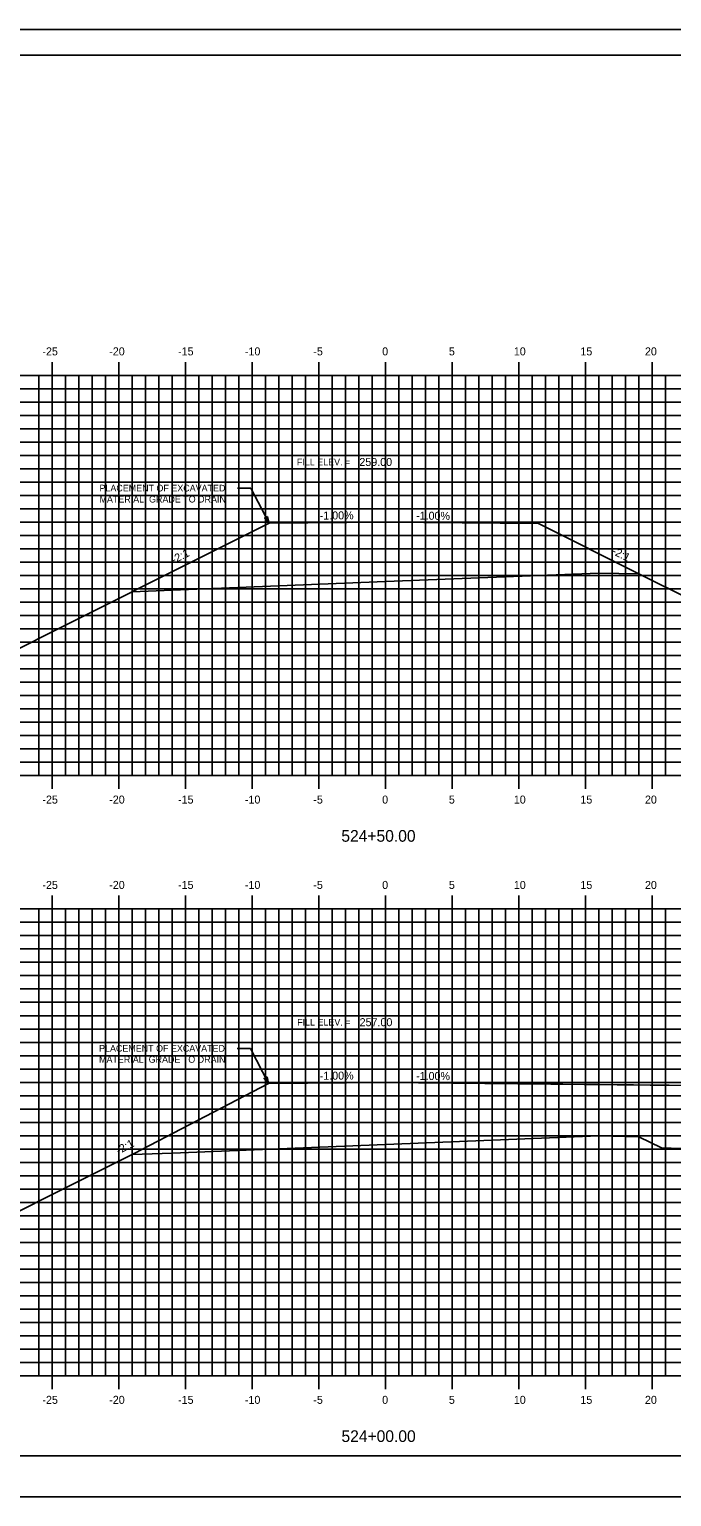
# Model space of a CAD drawing. Extents: x 1168600 to 1177589, y 610178 to 611246.
# Drawn here: x 1175478.4 to 1175526.6, y 610268.7 to 610378.7 of the extents above; entities that cross this region are included whole.
import ezdxf

# ---------------------------------------------------------------- set-up
doc = ezdxf.new("R2010")
doc.units = 0
for name, color, linetype in [('_Construction', 7, 'Continuous'), ('_Station Equation', 7, 'Continuous'), ('ANNOTATION', 7, 'Continuous'), ('BORDER', 7, 'Continuous'), ('D_Roadway_Centerline_Text', 7, 'Continuous'), ('D_Text_Standard', 7, 'Continuous'), ('H_V ANNOTATION', 7, 'Continuous'), ('MAJOR', 7, 'Continuous'), ('MINOR', 7, 'Continuous'), ('PLOT BOUNDARY', 7, 'Continuous')]:
    doc.layers.add(name, color=color, linetype=linetype)

msp = doc.modelspace()

# ---------------------------------------------------------------- linework, layer by layer
at = {"layer": '_Construction'}
for p, q in [((1175505.12, 610341.8), (1175496.39, 610341.71)), ((1175505.12, 610341.8), (1175516.58, 610341.69)), ((1175505.12, 610299.8), (1175496.36, 610299.71)), ((1175505.12, 610299.8), (1175544.81, 610299.4))]:
    msp.add_line(p, q, dxfattribs=at)
at = {"layer": '_Station Equation'}
msp.add_lwpolyline([(1175525.81, 610294.88), (1175536.74, 610294.51), (1175551.06, 610294.04), (1175553.14, 610293.97), (1175553.56, 610293.96), (1175556.21, 610293.92), (1175556.4, 610293.83), (1175559.56, 610292.31), (1175564.63, 610289.86), (1175564.65, 610290.02), (1175564.68, 610290.02), (1175565.31, 610289.71), (1175565.56, 610289.82), (1175565.82, 610289.89), (1175566.07, 610289.92), (1175566.32, 610289.9), (1175566.71, 610289.89), (1175574.47, 610289.2), (1175575.12, 610289.09)], dxfattribs=at)
at = {"layer": 'ANNOTATION'}
for p, q in [((1175494.03, 610344.35), (1175495.03, 610344.35)), ((1175496.39, 610341.71), (1175495.03, 610344.35)), ((1175494, 610302.35), (1175495, 610302.35)), ((1175496.36, 610299.71), (1175495, 610302.35))]:
    msp.add_line(p, q, dxfattribs=at)
for points in [[(1175496.27, 610342.22), (1175496.39, 610341.71), (1175496.05, 610342.1)], [(1175496.24, 610300.22), (1175496.36, 610299.71), (1175496.02, 610300.1)]]:
    msp.add_lwpolyline(points, close=True, dxfattribs=at)
at = {"layer": 'BORDER'}
for p, q in [((1175590.12, 610376.8), (1175430.12, 610376.8)), ((1175430.12, 610271.8), (1175590.12, 610271.8))]:
    msp.add_line(p, q, dxfattribs=at)
at = {"layer": 'D_Text_Standard'}
for points in [[(1175486.11, 610336.58), (1175489.54, 610338.29), (1175496.39, 610341.71), (1175505.12, 610341.8), (1175516.58, 610341.69), (1175524.11, 610337.92)], [(1175475.23, 610331.13), (1175482.58, 610334.81), (1175486.12, 610336.58), (1175489.12, 610336.7), (1175505.12, 610337.34), (1175521.12, 610337.98), (1175524.12, 610337.92), (1175528.08, 610335.94)], [(1175486.12, 610294.38), (1175486.28, 610294.47), (1175496.36, 610299.71), (1175505.12, 610299.8), (1175544.81, 610299.4), (1175552.9, 610295.5), (1175556.16, 610293.93)], [(1175473.1, 610287.88), (1175475.03, 610288.84), (1175482.58, 610292.62), (1175486.12, 610294.38), (1175489.12, 610294.5), (1175505.12, 610295.14), (1175521.12, 610295.78), (1175524.12, 610295.72), (1175525.81, 610294.88)]]:
    msp.add_lwpolyline(points, dxfattribs=at)
at = {"layer": 'MAJOR'}
for p, q in [((1175480.12, 610353.8), (1175480.12, 610352.8)), ((1175485.12, 610353.8), (1175485.12, 610352.8)), ((1175490.12, 610353.8), (1175490.12, 610352.8)), ((1175495.12, 610353.8), (1175495.12, 610352.8)), ((1175500.12, 610353.8), (1175500.12, 610352.8)), ((1175505.12, 610353.8), (1175505.12, 610352.8)), ((1175510.12, 610353.8), (1175510.12, 610352.8)), ((1175515.12, 610353.8), (1175515.12, 610352.8)), ((1175520.12, 610353.8), (1175520.12, 610352.8)), ((1175525.12, 610353.8), (1175525.12, 610352.8)), ((1175435.12, 610352.8), (1175575.12, 610352.8)), ((1175435.12, 610352.8), (1175575.12, 610352.8)), ((1175480.12, 610322.8), (1175480.12, 610352.8)), ((1175485.12, 610322.8), (1175485.12, 610352.8)), ((1175490.12, 610322.8), (1175490.12, 610352.8)), ((1175495.12, 610322.8), (1175495.12, 610352.8)), ((1175500.12, 610322.8), (1175500.12, 610352.8)), ((1175505.12, 610322.8), (1175505.12, 610352.8)), ((1175510.12, 610322.8), (1175510.12, 610352.8)), ((1175515.12, 610322.8), (1175515.12, 610352.8)), ((1175520.12, 610322.8), (1175520.12, 610352.8)), ((1175525.12, 610322.8), (1175525.12, 610352.8)), ((1175435.12, 610347.8), (1175575.12, 610347.8)), ((1175435.12, 610342.8), (1175575.12, 610342.8)), ((1175435.12, 610337.8), (1175575.12, 610337.8)), ((1175435.12, 610332.8), (1175575.12, 610332.8)), ((1175435.12, 610327.8), (1175575.12, 610327.8)), ((1175435.12, 610322.8), (1175575.12, 610322.8)), ((1175435.12, 610322.8), (1175575.12, 610322.8)), ((1175480.12, 610321.8), (1175480.12, 610322.8)), ((1175485.12, 610321.8), (1175485.12, 610322.8)), ((1175490.12, 610321.8), (1175490.12, 610322.8)), ((1175495.12, 610321.8), (1175495.12, 610322.8)), ((1175500.12, 610321.8), (1175500.12, 610322.8)), ((1175505.12, 610321.8), (1175505.12, 610322.8)), ((1175510.12, 610321.8), (1175510.12, 610322.8)), ((1175515.12, 610321.8), (1175515.12, 610322.8)), ((1175520.12, 610321.8), (1175520.12, 610322.8)), ((1175525.12, 610321.8), (1175525.12, 610322.8)), ((1175480.12, 610313.8), (1175480.12, 610312.8)), ((1175485.12, 610313.8), (1175485.12, 610312.8)), ((1175490.12, 610313.8), (1175490.12, 610312.8)), ((1175495.12, 610313.8), (1175495.12, 610312.8)), ((1175500.12, 610313.8), (1175500.12, 610312.8)), ((1175505.12, 610313.8), (1175505.12, 610312.8)), ((1175510.12, 610313.8), (1175510.12, 610312.8)), ((1175515.12, 610313.8), (1175515.12, 610312.8)), ((1175520.12, 610313.8), (1175520.12, 610312.8)), ((1175525.12, 610313.8), (1175525.12, 610312.8)), ((1175435.12, 610312.8), (1175575.12, 610312.8)), ((1175435.12, 610312.8), (1175575.12, 610312.8)), ((1175480.12, 610277.8), (1175480.12, 610312.8)), ((1175485.12, 610277.8), (1175485.12, 610312.8)), ((1175490.12, 610277.8), (1175490.12, 610312.8)), ((1175495.12, 610277.8), (1175495.12, 610312.8)), ((1175500.12, 610277.8), (1175500.12, 610312.8)), ((1175505.12, 610277.8), (1175505.12, 610312.8)), ((1175510.12, 610277.8), (1175510.12, 610312.8)), ((1175515.12, 610277.8), (1175515.12, 610312.8)), ((1175520.12, 610277.8), (1175520.12, 610312.8)), ((1175525.12, 610277.8), (1175525.12, 610312.8)), ((1175435.12, 610307.8), (1175575.12, 610307.8)), ((1175435.12, 610302.8), (1175575.12, 610302.8)), ((1175435.12, 610297.8), (1175575.12, 610297.8)), ((1175435.12, 610292.8), (1175575.12, 610292.8)), ((1175435.12, 610287.8), (1175575.12, 610287.8)), ((1175435.12, 610282.8), (1175575.12, 610282.8)), ((1175435.12, 610277.8), (1175575.12, 610277.8)), ((1175435.12, 610277.8), (1175575.12, 610277.8)), ((1175480.12, 610276.8), (1175480.12, 610277.8)), ((1175485.12, 610276.8), (1175485.12, 610277.8)), ((1175490.12, 610276.8), (1175490.12, 610277.8)), ((1175495.12, 610276.8), (1175495.12, 610277.8)), ((1175500.12, 610276.8), (1175500.12, 610277.8)), ((1175505.12, 610276.8), (1175505.12, 610277.8)), ((1175510.12, 610276.8), (1175510.12, 610277.8)), ((1175515.12, 610276.8), (1175515.12, 610277.8)), ((1175520.12, 610276.8), (1175520.12, 610277.8)), ((1175525.12, 610276.8), (1175525.12, 610277.8))]:
    msp.add_line(p, q, dxfattribs=at)
at = {"layer": 'MINOR'}
for p, q in [((1175479.12, 610322.8), (1175479.12, 610352.8)), ((1175481.12, 610322.8), (1175481.12, 610352.8)), ((1175482.12, 610322.8), (1175482.12, 610352.8)), ((1175483.12, 610322.8), (1175483.12, 610352.8)), ((1175484.12, 610322.8), (1175484.12, 610352.8)), ((1175486.12, 610322.8), (1175486.12, 610352.8)), ((1175487.12, 610322.8), (1175487.12, 610352.8)), ((1175488.12, 610322.8), (1175488.12, 610352.8)), ((1175489.12, 610322.8), (1175489.12, 610352.8)), ((1175491.12, 610322.8), (1175491.12, 610352.8)), ((1175492.12, 610322.8), (1175492.12, 610352.8)), ((1175493.12, 610322.8), (1175493.12, 610352.8)), ((1175494.12, 610322.8), (1175494.12, 610352.8)), ((1175496.12, 610322.8), (1175496.12, 610352.8)), ((1175497.12, 610322.8), (1175497.12, 610352.8)), ((1175498.12, 610322.8), (1175498.12, 610352.8)), ((1175499.12, 610322.8), (1175499.12, 610352.8)), ((1175501.12, 610322.8), (1175501.12, 610352.8)), ((1175502.12, 610322.8), (1175502.12, 610352.8)), ((1175503.12, 610322.8), (1175503.12, 610352.8)), ((1175504.12, 610322.8), (1175504.12, 610352.8)), ((1175506.12, 610322.8), (1175506.12, 610352.8)), ((1175507.12, 610322.8), (1175507.12, 610352.8)), ((1175508.12, 610322.8), (1175508.12, 610352.8)), ((1175509.12, 610322.8), (1175509.12, 610352.8)), ((1175511.12, 610322.8), (1175511.12, 610352.8)), ((1175512.12, 610322.8), (1175512.12, 610352.8)), ((1175513.12, 610322.8), (1175513.12, 610352.8)), ((1175514.12, 610322.8), (1175514.12, 610352.8)), ((1175516.12, 610322.8), (1175516.12, 610352.8)), ((1175517.12, 610322.8), (1175517.12, 610352.8)), ((1175518.12, 610322.8), (1175518.12, 610352.8)), ((1175519.12, 610322.8), (1175519.12, 610352.8)), ((1175521.12, 610322.8), (1175521.12, 610352.8)), ((1175522.12, 610322.8), (1175522.12, 610352.8)), ((1175523.12, 610322.8), (1175523.12, 610352.8)), ((1175524.12, 610322.8), (1175524.12, 610352.8)), ((1175526.12, 610322.8), (1175526.12, 610352.8)), ((1175435.12, 610351.8), (1175575.12, 610351.8)), ((1175435.12, 610350.8), (1175575.12, 610350.8)), ((1175435.12, 610349.8), (1175575.12, 610349.8)), ((1175435.12, 610348.8), (1175575.12, 610348.8)), ((1175435.12, 610346.8), (1175575.12, 610346.8)), ((1175435.12, 610345.8), (1175575.12, 610345.8)), ((1175435.12, 610344.8), (1175575.12, 610344.8)), ((1175435.12, 610343.8), (1175575.12, 610343.8)), ((1175435.12, 610341.8), (1175575.12, 610341.8)), ((1175435.12, 610340.8), (1175575.12, 610340.8)), ((1175435.12, 610339.8), (1175575.12, 610339.8)), ((1175435.12, 610338.8), (1175575.12, 610338.8)), ((1175435.12, 610336.8), (1175575.12, 610336.8)), ((1175435.12, 610335.8), (1175575.12, 610335.8)), ((1175435.12, 610334.8), (1175575.12, 610334.8)), ((1175435.12, 610333.8), (1175575.12, 610333.8)), ((1175435.12, 610331.8), (1175575.12, 610331.8)), ((1175435.12, 610330.8), (1175575.12, 610330.8)), ((1175435.12, 610329.8), (1175575.12, 610329.8)), ((1175435.12, 610328.8), (1175575.12, 610328.8)), ((1175435.12, 610326.8), (1175575.12, 610326.8)), ((1175435.12, 610325.8), (1175575.12, 610325.8)), ((1175435.12, 610324.8), (1175575.12, 610324.8)), ((1175435.12, 610323.8), (1175575.12, 610323.8)), ((1175479.12, 610277.8), (1175479.12, 610312.8)), ((1175481.12, 610277.8), (1175481.12, 610312.8)), ((1175482.12, 610277.8), (1175482.12, 610312.8)), ((1175483.12, 610277.8), (1175483.12, 610312.8)), ((1175484.12, 610277.8), (1175484.12, 610312.8)), ((1175486.12, 610277.8), (1175486.12, 610312.8)), ((1175487.12, 610277.8), (1175487.12, 610312.8)), ((1175488.12, 610277.8), (1175488.12, 610312.8)), ((1175489.12, 610277.8), (1175489.12, 610312.8)), ((1175491.12, 610277.8), (1175491.12, 610312.8)), ((1175492.12, 610277.8), (1175492.12, 610312.8)), ((1175493.12, 610277.8), (1175493.12, 610312.8)), ((1175494.12, 610277.8), (1175494.12, 610312.8)), ((1175496.12, 610277.8), (1175496.12, 610312.8)), ((1175497.12, 610277.8), (1175497.12, 610312.8)), ((1175498.12, 610277.8), (1175498.12, 610312.8)), ((1175499.12, 610277.8), (1175499.12, 610312.8)), ((1175501.12, 610277.8), (1175501.12, 610312.8)), ((1175502.12, 610277.8), (1175502.12, 610312.8)), ((1175503.12, 610277.8), (1175503.12, 610312.8)), ((1175504.12, 610277.8), (1175504.12, 610312.8)), ((1175506.12, 610277.8), (1175506.12, 610312.8)), ((1175507.12, 610277.8), (1175507.12, 610312.8)), ((1175508.12, 610277.8), (1175508.12, 610312.8)), ((1175509.12, 610277.8), (1175509.12, 610312.8)), ((1175511.12, 610277.8), (1175511.12, 610312.8)), ((1175512.12, 610277.8), (1175512.12, 610312.8)), ((1175513.12, 610277.8), (1175513.12, 610312.8)), ((1175514.12, 610277.8), (1175514.12, 610312.8)), ((1175516.12, 610277.8), (1175516.12, 610312.8)), ((1175517.12, 610277.8), (1175517.12, 610312.8)), ((1175518.12, 610277.8), (1175518.12, 610312.8)), ((1175519.12, 610277.8), (1175519.12, 610312.8)), ((1175521.12, 610277.8), (1175521.12, 610312.8)), ((1175522.12, 610277.8), (1175522.12, 610312.8)), ((1175523.12, 610277.8), (1175523.12, 610312.8)), ((1175524.12, 610277.8), (1175524.12, 610312.8)), ((1175526.12, 610277.8), (1175526.12, 610312.8)), ((1175435.12, 610311.8), (1175575.12, 610311.8)), ((1175435.12, 610310.8), (1175575.12, 610310.8)), ((1175435.12, 610309.8), (1175575.12, 610309.8)), ((1175435.12, 610308.8), (1175575.12, 610308.8)), ((1175435.12, 610306.8), (1175575.12, 610306.8)), ((1175435.12, 610305.8), (1175575.12, 610305.8)), ((1175435.12, 610304.8), (1175575.12, 610304.8)), ((1175435.12, 610303.8), (1175575.12, 610303.8)), ((1175435.12, 610301.8), (1175575.12, 610301.8)), ((1175435.12, 610300.8), (1175575.12, 610300.8)), ((1175435.12, 610299.8), (1175575.12, 610299.8)), ((1175435.12, 610298.8), (1175575.12, 610298.8)), ((1175435.12, 610296.8), (1175575.12, 610296.8)), ((1175435.12, 610295.8), (1175575.12, 610295.8)), ((1175435.12, 610294.8), (1175575.12, 610294.8)), ((1175435.12, 610293.8), (1175575.12, 610293.8)), ((1175435.12, 610291.8), (1175575.12, 610291.8)), ((1175435.12, 610290.8), (1175575.12, 610290.8)), ((1175435.12, 610289.8), (1175575.12, 610289.8)), ((1175435.12, 610288.8), (1175575.12, 610288.8)), ((1175435.12, 610286.8), (1175575.12, 610286.8)), ((1175435.12, 610285.8), (1175575.12, 610285.8)), ((1175435.12, 610284.8), (1175575.12, 610284.8)), ((1175435.12, 610283.8), (1175575.12, 610283.8)), ((1175435.12, 610281.8), (1175575.12, 610281.8)), ((1175435.12, 610280.8), (1175575.12, 610280.8)), ((1175435.12, 610279.8), (1175575.12, 610279.8)), ((1175435.12, 610278.8), (1175575.12, 610278.8))]:
    msp.add_line(p, q, dxfattribs=at)
at = {"layer": 'PLOT BOUNDARY'}
msp.add_lwpolyline([(1175422.02, 610268.74), (1175592.02, 610268.74), (1175592.02, 610378.74), (1175422.02, 610378.74)], close=True, dxfattribs=at)

# ---------------------------------------------------------------- texts
at = {"layer": 'ANNOTATION'}
for s, p in [('FILL ELEV. =', (1175498.48, 610346.06)), ('PLACEMENT OF EXCAVATED ', (1175483.68, 610344.1)), ('MATERIAL, GRADE TO DRAIN', (1175483.68, 610343.27)), ('FILL ELEV. =', (1175498.5, 610304.06)), ('PLACEMENT OF EXCAVATED ', (1175483.65, 610302.1)), ('MATERIAL, GRADE TO DRAIN', (1175483.65, 610301.27))]:
    msp.add_text(s, height=0.5, dxfattribs=at).set_placement(p)
for s, rotation, p in [('-1.00%', 0.5729, (1175500.19, 610341.99)), ('-1.00%', 359.4271, (1175507.41, 610341.99)), ('-2:1', 26.5643, (1175489.25, 610338.67)), ('-2:1', 333.4349, (1175522.04, 610339.44)), ('-1.00%', 0.5729, (1175500.19, 610299.99)), ('-1.00%', 359.4271, (1175507.41, 610299.99)), ('-2:1', 27.7462, (1175485.11, 610294.39))]:
    msp.add_text(s, height=0.6, rotation=rotation, dxfattribs=at).set_placement(p)
at = {"layer": 'D_Roadway_Centerline_Text'}
for s, p in [('259.00', (1175503.16, 610346.01)), ('257.00', (1175503.18, 610304.01))]:
    msp.add_text(s, height=0.6, dxfattribs=at).set_placement(p)
at = {"layer": 'D_Text_Standard'}
for s, p in [('C', (1175505.11, 610337.34)), ('L', (1175505.12, 610337.33))]:
    msp.add_text(s, height=0.0146, dxfattribs=at).set_placement(p)
at = {"layer": 'H_V ANNOTATION'}
for s, height, p in [('-25', 0.6, (1175479.4, 610354.3)), ('-20', 0.6, (1175484.41, 610354.3)), ('-15', 0.6, (1175489.57, 610354.3)), ('-10', 0.6, (1175494.58, 610354.3)), ('-5', 0.6, (1175499.71, 610354.3)), ('0', 0.6, (1175504.87, 610354.3)), ('5', 0.6, (1175509.87, 610354.3)), ('10', 0.6, (1175514.74, 610354.3)), ('15', 0.6, (1175519.73, 610354.3)), ('20', 0.6, (1175524.57, 610354.3)), ('-25', 0.6, (1175479.4, 610320.7)), ('-20', 0.6, (1175484.41, 610320.7)), ('-15', 0.6, (1175489.57, 610320.7)), ('-10', 0.6, (1175494.58, 610320.7)), ('-5', 0.6, (1175499.71, 610320.7)), ('0', 0.6, (1175504.87, 610320.7)), ('5', 0.6, (1175509.87, 610320.7)), ('10', 0.6, (1175514.74, 610320.7)), ('15', 0.6, (1175519.73, 610320.7)), ('20', 0.6, (1175524.57, 610320.7)), ('524+50.00', 0.875, (1175501.81, 610317.84)), ('-25', 0.6, (1175479.4, 610314.3)), ('-20', 0.6, (1175484.41, 610314.3)), ('-15', 0.6, (1175489.57, 610314.3)), ('-10', 0.6, (1175494.58, 610314.3)), ('-5', 0.6, (1175499.71, 610314.3)), ('0', 0.6, (1175504.87, 610314.3)), ('5', 0.6, (1175509.87, 610314.3)), ('10', 0.6, (1175514.74, 610314.3)), ('15', 0.6, (1175519.73, 610314.3)), ('20', 0.6, (1175524.57, 610314.3)), ('-25', 0.6, (1175479.4, 610275.7)), ('-20', 0.6, (1175484.41, 610275.7)), ('-15', 0.6, (1175489.57, 610275.7)), ('-10', 0.6, (1175494.58, 610275.7)), ('-5', 0.6, (1175499.71, 610275.7)), ('0', 0.6, (1175504.87, 610275.7)), ('5', 0.6, (1175509.87, 610275.7)), ('10', 0.6, (1175514.74, 610275.7)), ('15', 0.6, (1175519.73, 610275.7)), ('20', 0.6, (1175524.57, 610275.7)), ('524+00.00', 0.875, (1175501.82, 610272.84))]:
    msp.add_text(s, height=height, dxfattribs=at).set_placement(p)

doc.saveas('drawing.dxf')
